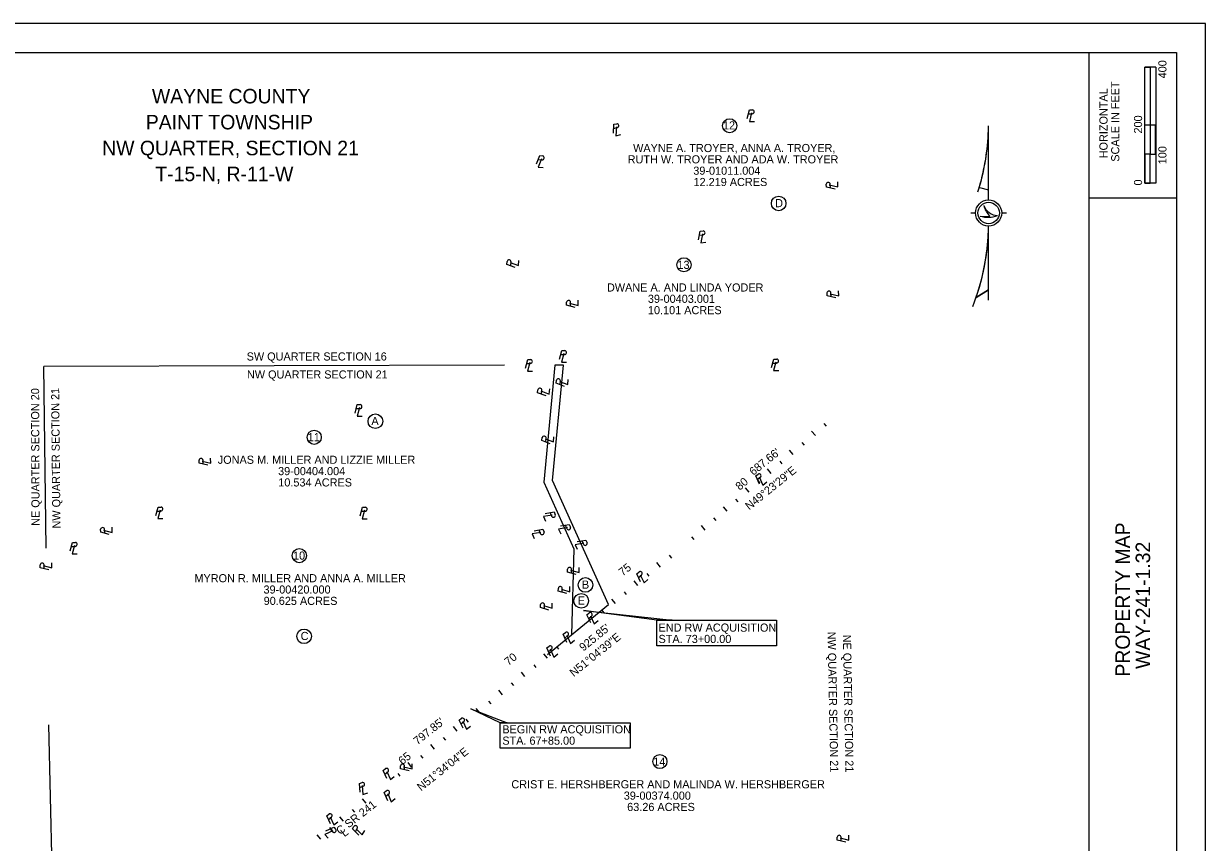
# Model space of a CAD drawing. Extents: x 2180380 to 2187180, y 367894 to 372294.
# Drawn here: x 2183109 to 2187180, y 369473 to 372294 of the extents above; entities that cross this region are included whole.
import ezdxf

# ---------------------------------------------------------------- set-up
doc = ezdxf.new("R2010")
doc.units = 0
for name, color, linetype in [('Default', 7, 'Continuous'), ('DR_X_Elev_Flow', 7, 'Continuous'), ('PM_X_Surveyed_Line', 7, 'Continuous'), ('PV_X_EOP', 7, 'Continuous'), ('PV_X_Shoulder', 7, 'Continuous'), ('RD_X_Cells', 7, 'Continuous'), ('SN_X_Public', 7, 'Continuous'), ('SV_X_Control_Cells_Found', 7, 'Continuous'), ('SV_X_Random_Point', 7, 'Continuous'), ('UT_X_Gas_Cells', 7, 'Continuous'), ('UT_X_Telecom_Cells', 7, 'Continuous'), ('VG_X_Cells', 7, 'Continuous')]:
    doc.layers.add(name, color=color, linetype=linetype)

msp = doc.modelspace()

# ---------------------------------------------------------------- linework, layer by layer
at = {"layer": 'Default'}
for points in [[(2185290.3, 370238.7), (2185038.3, 370271.8), (2185343.4, 370238.7)], [(2185290.3, 370238.7), (2185703, 370238.7), (2185703, 370150.5), (2185290.3, 370150.5)], [(2184750.4, 369884.7), (2184650.2, 369932.6), (2184775, 369884.7)], [(2184750.4, 369884.7), (2185198.3, 369884.7), (2185198.3, 369797.9), (2184750.4, 369797.9)]]:
    msp.add_lwpolyline(points, close=True, dxfattribs=at)
for centre in [(2185541.3, 371942.5), (2185383.9, 371463.3), (2184110.2, 370868.8), (2184059, 370460.9), (2185300.9, 369751.4)]:
    msp.add_circle(centre, 24.3, dxfattribs=at)
at = {"layer": 'DR_X_Elev_Flow'}
for p, q in [((2186971.2, 371744.4), (2186971.2, 372144.4)), ((2187008.7, 372144.4), (2186971.2, 372144.4)), ((2186971.2, 371944.4), (2186971.2, 372144.4)), ((2186971.2, 372144.4), (2186989.9, 372144.4)), ((2186989.9, 372144.4), (2186990, 372144.4)), ((2186990, 372144.4), (2186990, 371944.4)), ((2187008.7, 372144.4), (2187008.7, 371744.4)), ((2186433.3, 371686.8), (2186433.3, 371941.8)), ((2186990, 371944.4), (2186971.2, 371944.4)), ((2187008.5, 371944.4), (2186989.9, 371944.4)), ((2186989.9, 371944.4), (2186989.9, 371844.4)), ((2187008.5, 371844.4), (2187008.5, 371944.4)), ((2186989.9, 371844.4), (2186971.2, 371844.4)), ((2186971.2, 371844.4), (2186971.2, 371744.4)), ((2186989.9, 371844.4), (2187008.5, 371844.4)), ((2186989.9, 371744.4), (2186989.9, 371844.4)), ((2186401.4, 371729.8), (2186433.3, 371721.1)), ((2187008.7, 371744.4), (2186971.2, 371744.4)), ((2186971.2, 371744.4), (2186989.9, 371744.4)), ((2186372.3, 371641.8), (2186388.3, 371641.8)), ((2186478.3, 371641.8), (2186494.3, 371641.8)), ((2186433.3, 371341.8), (2186433.3, 371596.8)), ((2186433.3, 371376.8), (2186390.4, 371351.1))]:
    msp.add_line(p, q, dxfattribs=at)
for points in [[(2186401.2, 371729.9), (2186401.4, 371729.8), (2186433.3, 371721.1), (2186433.3, 371941.8)], [(2186390.4, 371351.1), (2186433.3, 371376.8), (2186433.3, 371596.8)]]:
    msp.add_lwpolyline(points, dxfattribs=at)
for radius in [45, 37]:
    msp.add_circle((2186433.3, 371641.8), radius, dxfattribs=at)
for centre, radius, start, end in [((2185644.8, 371952.9), 788.5, 342.4153, 359.1947), ((2185644.8, 371952.9), 788.5, 343.5754, 359.1947), ((2186464.8, 371684.3), 51, 199.1575, 269.3709), ((2186486.5, 371683.6), 71.7, 192.8556, 227.3141), ((2186431.1, 371717.6), 90.5, 252.4874, 291.486), ((2186422.3, 371744.1), 114.3, 260.7277, 277.8734), ((2185644.8, 371607.9), 788.5, 338.5054, 359.1947), ((2185644.8, 371607.9), 788.5, 340.9936, 359.1947)]:
    msp.add_arc(centre, radius, start, end, dxfattribs=at)
at = {"layer": 'PM_X_Surveyed_Line'}
for p, q in [((2185874.4, 370907.2), (2185866.6, 370916.3)), ((2185836.4, 370874.7), (2185823.4, 370889.9)), ((2185760.5, 370809.6), (2185747.5, 370824.8)), ((2185798.5, 370842.1), (2185790.6, 370851.3)), ((2185722.5, 370777.1), (2185714.7, 370786.2)), ((2185684.6, 370744.5), (2185671.6, 370759.7)), ((2185646.6, 370712), (2185638.8, 370721.1)), ((2185608.7, 370679.4), (2185595.6, 370694.6)), ((2185532.7, 370614.3), (2185519.7, 370629.5)), ((2185570.7, 370646.9), (2185562.9, 370656)), ((2185494.8, 370581.8), (2185487, 370590.9)), ((2185456.8, 370549.2), (2185443.8, 370564.4)), ((2185418.9, 370516.7), (2185411.1, 370525.8))]:
    msp.add_line(p, q, dxfattribs=at)
at = {"layer": 'PV_X_EOP'}
msp.add_lwpolyline([(2184969.3, 371117.5), (2184939.1, 371117.6), (2184901, 370714.4), (2185004.7, 370484.7), (2184997, 370187.9), (2185124.2, 370293), (2184931.6, 370719.6), (2184969.3, 371117.5)], dxfattribs=at)
at = {"layer": 'PV_X_Shoulder'}
for centre in [(2185710.1, 371674.6), (2184321, 370924.1), (2185044.5, 370359.9), (2185030, 370305.2), (2184075.6, 370182.9)]:
    msp.add_circle(centre, 25.2, dxfattribs=at)
at = {"layer": 'RD_X_Cells'}
for p, q in [((2186779.9, 367994.4), (2186779.9, 372194.4)), ((2186779.9, 371694.4), (2187079.9, 371694.4))]:
    msp.add_line(p, q, dxfattribs=at)
msp.add_lwpolyline([(2180679.9, 372194.4), (2187079.9, 372194.4), (2187079.9, 367994.4), (2180679.9, 367994.4)], close=True, dxfattribs=at)
at = {"layer": 'SN_X_Public'}
for p, q in [((2185342, 370452.7), (2185334.5, 370462.1)), ((2185303.1, 370421.3), (2185290.5, 370436.9)), ((2185264.2, 370389.9), (2185256.7, 370399.3)), ((2185186.4, 370327.1), (2185178.9, 370336.4)), ((2185225.3, 370358.5), (2185212.7, 370374.1)), ((2185147.5, 370295.7), (2185134.9, 370311.2)), ((2185108.6, 370264.3), (2185101.1, 370273.6)), ((2184953, 370138.6), (2184945.5, 370147.9)), ((2184914.1, 370107.2), (2184901.6, 370122.8)), ((2184836.3, 370044.4), (2184823.8, 370059.9)), ((2184875.2, 370075.8), (2184867.7, 370085.1)), ((2184797.4, 370013), (2184789.9, 370022.3)), ((2184758.5, 369981.5), (2184746, 369997.1)), ((2184680.7, 369918.7), (2184668.2, 369934.3)), ((2184719.6, 369950.1), (2184712.1, 369959.5)), ((2184641.7, 369887.5), (2184634.2, 369896.9)), ((2184602.5, 369856.4), (2184590.1, 369872.1)), ((2184524.2, 369794.2), (2184511.8, 369809.9)), ((2184563.4, 369825.3), (2184555.9, 369834.7)), ((2184485, 369763.1), (2184477.6, 369772.5)), ((2184445.9, 369732.1), (2184433.4, 369747.7)), ((2184406.7, 369701), (2184399.2, 369710.4)), ((2184289.2, 369607.8), (2184276.8, 369623.4)), ((2184250, 369576.7), (2184242.6, 369586.1)), ((2184171.7, 369514.5), (2184164.2, 369523.9)), ((2184210.8, 369545.6), (2184198.4, 369561.3)), ((2184132.5, 369483.4), (2184120.1, 369499.1))]:
    msp.add_line(p, q, dxfattribs=at)
at = {"layer": 'SV_X_Control_Cells_Found'}
for p, q in [((2184765.3, 371117), (2183179.4, 371113.1)), ((2183187.5, 370486.8), (2183179.4, 371113.1)), ((2183195.4, 369878.1), (2183219.4, 368766.9))]:
    msp.add_line(p, q, dxfattribs=at)
at = {"layer": 'SV_X_Random_Point'}
msp.add_lwpolyline([(2180379.9, 367894.4), (2187179.9, 367894.4), (2187179.9, 372294.4), (2180379.9, 372294.4)], close=True, dxfattribs=at)
at = {"layer": 'UT_X_Telecom_Cells'}
for p, q in [((2185606.3, 371983.8), (2185619.3, 371983.8)), ((2185614.3, 371977.6), (2185614.3, 371977.6)), ((2185141.6, 371933.3), (2185154.3, 371935.9)), ((2185150.7, 371928.8), (2185150.7, 371928.8)), ((2184882.1, 371826.4), (2184894.9, 371824.9)), ((2184889.3, 371819.3), (2184889.3, 371819.3)), ((2185888.2, 371727.7), (2185887.6, 371740.7)), ((2185894.1, 371736), (2185894.1, 371736)), ((2185437.3, 371565.3), (2185450.2, 371566.4)), ((2185445.8, 371559.8), (2185445.8, 371559.8)), ((2184787.1, 371459.8), (2184788.3, 371472.8)), ((2184794, 371467.3), (2184794, 371467.3)), ((2185890.6, 371353), (2185890.3, 371365.9)), ((2185896.7, 371361.1), (2185896.7, 371361.1)), ((2184993.3, 371320.8), (2184993.4, 371333.8)), ((2184999.6, 371328.8), (2184999.6, 371328.8)), ((2184959.3, 371153.7), (2184972.3, 371153.7)), ((2184842.1, 371123.4), (2184855.1, 371123.4)), ((2184850.1, 371117.2), (2184850.1, 371117.2)), ((2184967.3, 371147.5), (2184967.3, 371147.5)), ((2185689.9, 371124.7), (2185702.8, 371124.7)), ((2185697.9, 371118.5), (2185697.9, 371118.5)), ((2184893.3, 371017.6), (2184894.5, 371030.5)), ((2184957.1, 371050.1), (2184958.3, 371063)), ((2184964.1, 371057.5), (2184964.1, 371057.5)), ((2184900.2, 371025), (2184900.2, 371025)), ((2184255, 370967.8), (2184268, 370967.8)), ((2184263, 370961.6), (2184263, 370961.6)), ((2184907.8, 370852.3), (2184909, 370865.2)), ((2184914.7, 370859.7), (2184914.7, 370859.7)), ((2183727.5, 370776.3), (2183727.3, 370789.2)), ((2183733.6, 370784.4), (2183733.6, 370784.4)), ((2185636.9, 370722.8), (2185646.9, 370731)), ((2185647, 370723), (2185647, 370723)), ((2183569.1, 370614.7), (2183582.1, 370614.7)), ((2183577.1, 370608.5), (2183577.1, 370608.5)), ((2184272.9, 370613.9), (2184285.8, 370613.9)), ((2184280.9, 370607.7), (2184280.9, 370607.7)), ((2184920.1, 370599.2), (2184920.1, 370599.2)), ((2184922.5, 370609), (2184927.8, 370597.2)), ((2183388.5, 370537.9), (2183388.3, 370550.8)), ((2183394.6, 370546), (2183394.6, 370546)), ((2184883.6, 370549.4), (2184888.9, 370537.5)), ((2184972.5, 370556), (2184972.5, 370556)), ((2184974.9, 370565.8), (2184980.3, 370554)), ((2184881.2, 370539.5), (2184881.2, 370539.5)), ((2185029.6, 370502.1), (2185029.6, 370502.1)), ((2185032, 370511.9), (2185037.4, 370500.1)), ((2183273.8, 370493), (2183286.7, 370493)), ((2183281.8, 370486.7), (2183281.8, 370486.7)), ((2183180.2, 370415.8), (2183180, 370428.7)), ((2183186.3, 370423.9), (2183186.3, 370423.9)), ((2184996.3, 370400.4), (2184996.6, 370413.4)), ((2185002.7, 370408.3), (2185002.7, 370408.3)), ((2185227.4, 370385.7), (2185237.3, 370394.1)), ((2185237.5, 370386.2), (2185237.5, 370386.2)), ((2184964.6, 370334.6), (2184964.9, 370347.6)), ((2184971, 370342.5), (2184971, 370342.5)), ((2184903.1, 370277.8), (2184903.4, 370290.7)), ((2184909.5, 370285.6), (2184909.5, 370285.6)), ((2185040.9, 370224.1), (2184913.8, 370119)), ((2185055.7, 370244.5), (2185065.7, 370252.8)), ((2185065.9, 370244.8), (2185065.9, 370244.8)), ((2184974, 370176.9), (2184984, 370185.2)), ((2184984.2, 370177.2), (2184984.2, 370177.2)), ((2184917.2, 370129.9), (2184927.2, 370138.2)), ((2184927.4, 370130.3), (2184927.4, 370130.3)), ((2184615.8, 369880.8), (2184625.7, 369889.1)), ((2184625.9, 369881.2), (2184625.9, 369881.2)), ((2184421.6, 369722.9), (2184421.3, 369735.9)), ((2184427.6, 369731.1), (2184427.6, 369731.1)), ((2184353.9, 369707.7), (2184363.9, 369715.8)), ((2184364, 369707.9), (2184364, 369707.9)), ((2184267, 369661.8), (2184279.2, 369666)), ((2184276.6, 369658.5), (2184276.6, 369658.5)), ((2184357.4, 369631.6), (2184367.6, 369639.6)), ((2184367.6, 369631.7), (2184367.6, 369631.7)), ((2184159.5, 369551.3), (2184169.5, 369559.4)), ((2184169.6, 369551.5), (2184169.6, 369551.5)), ((2184165.3, 369519.1), (2184173.6, 369509.1)), ((2184165.6, 369508.9), (2184165.6, 369508.9)), ((2184251.9, 369509), (2184258.4, 369520.2)), ((2184261.3, 369512.8), (2184261.3, 369512.8)), ((2185925.5, 369477.4), (2185925.2, 369490.4)), ((2185931.5, 369485.5), (2185931.5, 369485.5))]:
    msp.add_line(p, q, dxfattribs=at)
for points in [[(2185602.1, 371967.9), (2185609.9, 371997.6), (2185620.3, 371997.6)], [(2185617, 371987.2), (2185609.1, 371957.6), (2185626.6, 371957.6)], [(2185140.7, 371916.8), (2185142.3, 371947.5), (2185152.4, 371949.6)], [(2185151.3, 371938.8), (2185149.6, 371908.2), (2185166.7, 371911.8)], [(2184876.1, 371811.1), (2184887.2, 371839.6), (2184897.5, 371838.4)], [(2184893.1, 371828.5), (2184881.8, 371800.1), (2184899.2, 371798)], [(2185904.3, 371724.2), (2185874.3, 371730.8), (2185873.9, 371741.1)], [(2185884.4, 371738.3), (2185914.2, 371731.6), (2185913.5, 371749.1)], [(2185434.4, 371549.1), (2185439.8, 371579.3), (2185450.1, 371580.1)], [(2185447.7, 371569.6), (2185442.2, 371539.4), (2185459.6, 371540.9)], [(2184784.7, 371470.8), (2184813.5, 371460.3), (2184815, 371477.7)], [(2184802.6, 371454.3), (2184773.8, 371464.7), (2184774.7, 371475)], [(2185906.6, 371349.2), (2185876.8, 371356.2), (2185876.6, 371366.6)], [(2185887, 371363.6), (2185916.8, 371356.4), (2185916.3, 371373.8)], [(2185009.2, 371316.5), (2184979.6, 371324.5), (2184979.7, 371334.8)], [(2184990, 371331.5), (2185019.6, 371323.4), (2185019.7, 371340.9)], [(2184955.1, 371137.8), (2184962.9, 371167.4), (2184973.2, 371167.4)], [(2184970, 371157.1), (2184962.1, 371127.5), (2184979.5, 371127.5)], [(2184837.9, 371107.5), (2184845.7, 371137.2), (2184856, 371137.2)], [(2184852.8, 371126.8), (2184844.9, 371097.2), (2184862.3, 371097.2)], [(2185685.7, 371108.8), (2185693.5, 371138.5), (2185703.8, 371138.4)], [(2185700.5, 371128.1), (2185692.6, 371098.5), (2185710.1, 371098.5)], [(2184908.7, 371011.9), (2184879.9, 371022.5), (2184880.9, 371032.8)], [(2184890.9, 371028.6), (2184919.6, 371017.9), (2184921.3, 371035.3)], [(2184972.5, 371044.4), (2184943.8, 371055), (2184944.8, 371065.3)], [(2184954.7, 371061), (2184983.4, 371050.4), (2184985.1, 371067.8)], [(2184250.8, 370951.9), (2184258.6, 370981.5), (2184269, 370981.5)], [(2184265.7, 370971.2), (2184257.8, 370941.6), (2184275.3, 370941.6)], [(2184923.2, 370846.6), (2184894.5, 370857.2), (2184895.4, 370867.5)], [(2184905.4, 370863.2), (2184934.1, 370852.6), (2184935.8, 370870)], [(2183743.5, 370772.3), (2183713.7, 370779.7), (2183713.6, 370790)], [(2183724, 370786.9), (2183753.7, 370779.4), (2183753.4, 370796.8)], [(2185643.7, 370707.8), (2185630.9, 370735.7), (2185638.9, 370742.2)], [(2185643, 370732.2), (2185655.7, 370704.3), (2185669.2, 370715.4)], [(2183564.9, 370598.8), (2183572.7, 370628.5), (2183583, 370628.5)], [(2184268.7, 370598), (2184276.5, 370627.6), (2184286.8, 370627.6)], [(2183579.8, 370618.1), (2183571.9, 370588.5), (2183589.3, 370588.5)], [(2184283.5, 370617.3), (2184275.6, 370587.7), (2184293.1, 370587.7)], [(2184930, 370600.7), (2184899.7, 370595.7), (2184906.9, 370579.8)], [(2184906.3, 370606.3), (2184936.5, 370611.4), (2184940.7, 370602)], [(2183404.4, 370533.9), (2183374.7, 370541.3), (2183374.6, 370551.6)], [(2183384.9, 370548.5), (2183414.6, 370541), (2183414.4, 370558.5)], [(2184891.1, 370541), (2184860.9, 370536.1), (2184868.1, 370520.1)], [(2184867.4, 370546.6), (2184897.6, 370551.7), (2184901.9, 370542.3)], [(2184982.4, 370557.5), (2184952.2, 370552.5), (2184959.4, 370536.6)], [(2184958.7, 370563.1), (2184988.9, 370568.2), (2184993.2, 370558.8)], [(2183269.6, 370477), (2183277.4, 370506.7), (2183287.7, 370506.7)], [(2185039.5, 370503.6), (2185009.3, 370498.6), (2185016.5, 370482.7)], [(2185015.8, 370509.2), (2185046, 370514.3), (2185050.3, 370504.9)], [(2183284.4, 370496.3), (2183276.5, 370466.8), (2183294, 370466.8)], [(2183196.2, 370411.9), (2183166.4, 370419.1), (2183166.2, 370429.4)], [(2183176.6, 370426.4), (2183206.4, 370419.1), (2183206, 370436.6)], [(2184993.2, 370411.2), (2185022.6, 370402.5), (2185023, 370420)], [(2185012.1, 370395.8), (2184982.7, 370404.4), (2184983, 370414.7)], [(2185234.5, 370370.9), (2185221.2, 370398.6), (2185229.1, 370405.2)], [(2185233.3, 370395.2), (2185246.4, 370367.6), (2185259.7, 370378.9)], [(2184980.4, 370330), (2184951, 370338.6), (2184951.2, 370348.9)], [(2184961.5, 370345.4), (2184990.8, 370336.7), (2184991.3, 370354.2)], [(2184900, 370288.6), (2184929.4, 370279.9), (2184929.8, 370297.3)], [(2184918.9, 370273.2), (2184889.5, 370281.8), (2184889.7, 370292.1)], [(2185062.6, 370229.5), (2185049.8, 370257.4), (2185057.7, 370264)], [(2185061.8, 370253.9), (2185074.6, 370226.1), (2185088, 370237.2)], [(2184980.9, 370162), (2184968, 370189.8), (2184976, 370196.4)], [(2184980.1, 370186.3), (2184992.8, 370158.5), (2185006.3, 370169.6)], [(2184924.1, 370115), (2184911.3, 370142.8), (2184919.2, 370149.4)], [(2184923.3, 370139.4), (2184936, 370111.5), (2184949.5, 370122.7)], [(2184622.8, 369865.9), (2184609.7, 369893.7), (2184617.7, 369900.3)], [(2184621.8, 369890.3), (2184634.8, 369862.5), (2184648.1, 369873.7)], [(2184360.6, 369692.6), (2184348, 369720.6), (2184356.1, 369727.1)], [(2184437.6, 369719.2), (2184407.8, 369726.2), (2184407.5, 369736.5)], [(2184418, 369733.5), (2184447.7, 369726.4), (2184447.3, 369743.9)], [(2184360, 369717), (2184372.5, 369689), (2184386.1, 369700)], [(2184268.2, 369645.4), (2184265.9, 369675.9), (2184275.7, 369679.3)], [(2184276, 369668.4), (2184278.1, 369637.9), (2184294.6, 369643.6)], [(2184364.1, 369616.5), (2184351.7, 369644.6), (2184359.8, 369651)], [(2184363.7, 369640.8), (2184375.9, 369612.8), (2184389.6, 369623.6)], [(2184166.2, 369536.3), (2184153.6, 369564.2), (2184161.7, 369570.7)], [(2184150.4, 369512.1), (2184178.2, 369525.1), (2184184.8, 369517.1)], [(2184165.7, 369560.6), (2184178.1, 369532.7), (2184191.7, 369543.7)], [(2184263.6, 369497.4), (2184241.8, 369519), (2184247, 369528)], [(2184174.7, 369513), (2184146.9, 369500.2), (2184158.1, 369486.8)], [(2184254.4, 369520), (2184276, 369498.3), (2184284.7, 369513.5)], [(2185941.5, 369473.5), (2185911.7, 369480.8), (2185911.5, 369491.1)], [(2185921.9, 369488), (2185951.6, 369480.7), (2185951.3, 369498.2)]]:
    msp.add_lwpolyline(points, dxfattribs=at)
for centre, start, end in [((2185619.2, 371990.7), 270.471, 81.3281), ((2185152.8, 371942.7), 282.2766, 93.1337), ((2184895.7, 371831.8), 263.8916, 74.7487), ((2185880.7, 371740.4), 2.8769, 173.734), ((2185449.6, 371573.3), 275.138, 85.9951), ((2184781.4, 371473.3), 355.3999, 166.2571), ((2185883.4, 371365.7), 1.867, 172.7241), ((2184986.5, 371333.7), 0.1769, 171.034), ((2184972.2, 371160.6), 270.471, 81.3281), ((2184855, 371130.3), 270.471, 81.3281), ((2185702.8, 371131.6), 270.471, 81.3281), ((2184951.4, 371063.6), 355.0649, 165.9221), ((2184887.6, 371031.1), 355.0649, 165.9221), ((2184267.9, 370974.7), 270.471, 81.3281), ((2184902.1, 370865.8), 355.0649, 165.9221), ((2183720.5, 370789.1), 1.2358, 172.0929), ((2185642.5, 370736.3), 309.9088, 120.7659), ((2183582, 370621.6), 270.471, 81.3281), ((2184285.8, 370620.8), 270.471, 81.3281), ((2184934.1, 370600.1), 204.7708, 15.6279), ((2183381.4, 370550.7), 1.2358, 172.0929), ((2184895.2, 370540.4), 204.7708, 15.6279), ((2184986.5, 370556.9), 204.7708, 15.6279), ((2183286.7, 370499.9), 270.471, 81.3281), ((2185043.6, 370503), 204.7708, 15.6279), ((2183173.1, 370428.5), 1.6757, 172.5328), ((2184989.7, 370413.5), 358.9838, 169.8409), ((2185232.7, 370399.4), 310.8028, 121.6599), ((2184958, 370347.7), 358.9838, 169.8409), ((2184896.5, 370290.9), 358.9838, 169.8409), ((2185061.3, 370258), 310.0599, 120.9171), ((2184979.6, 370190.5), 310.0599, 120.9171), ((2184922.8, 370143.5), 310.0599, 120.9171), ((2184621.3, 369894.4), 310.4572, 121.3143), ((2184359.6, 369721.1), 309.5038, 120.3609), ((2184414.4, 369735.7), 1.9741, 172.8312), ((2184276.9, 369672.5), 289.3975, 100.2547), ((2184363.3, 369645), 308.9353, 119.7925), ((2184165.2, 369564.8), 309.5038, 120.3609), ((2184252.4, 369523.6), 330.5024, 141.3595), ((2184178.8, 369513.6), 220.1842, 31.0413), ((2185918.3, 369490.2), 1.603, 172.4601)]:
    msp.add_arc(centre, 6.9, start, end, dxfattribs=at)

# ---------------------------------------------------------------- texts
at = {"layer": 'Default'}
for s, p in [('12', (2185518.3, 371929.7)), ('WAYNE A. TROYER, ANNA A. TROYER, ', (2185208.7, 371851.7)), ('RUTH W. TROYER AND ADA W. TROYER', (2185189.9, 371812.7)), ('39-01011.004', (2185416, 371773.6)), ('12.219 ACRES', (2185416.8, 371734.6)), ('13', (2185361.5, 371449.1)), ('DWANE A. AND LINDA YODER', (2185118.7, 371371.1)), ('39-00403.001', (2185259.6, 371332.1)), ('10.101 ACRES', (2185259.8, 371293)), ('SW QUARTER SECTION 16', (2183877.5, 371133.4)), ('NW QUARTER SECTION 21', (2183878.6, 371071.4)), ('11', (2184088, 370855.4)), ('JONAS M. MILLER AND LIZZIE MILLER', (2183778.1, 370777.4)), ('39-00404.004', (2183985.8, 370738.3)), ('10.534 ACRES', (2183986.5, 370699.3)), ('10', (2184037.3, 370447.2)), ('MYRON R. MILLER AND ANNA A. MILLER', (2183697.7, 370369.2)), ('39-00420.000', (2183935.6, 370330.2)), ('90.625 ACRES', (2183936.2, 370291.1)), ('END RW ACQUISITION', (2185296.2, 370198.9)), ('STA. 73+00.00', (2185296.2, 370159.9)), ('BEGIN RW ACQUISITION', (2184758.2, 369848.4)), ('STA. 67+85.00', (2184758.2, 369809.4)), ('14', (2185278.1, 369737)), ('CRIST E. HERSHBERGER AND MALINDA W. HERSHBERGER', (2184789.4, 369659)), ('39-00374.000', (2185176.5, 369619.9)), ('63.26 ACRES', (2185188.3, 369580.9))]:
    msp.add_text(s, height=28, dxfattribs=at).set_placement(p)
for s, rotation, p in [('NE QUARTER SECTION 20', 90.1877, (2183164.3, 370563.6)), ('NW QUARTER SECTION 21', 90.5777, (2183236.5, 370554.6)), ('NW QUARTER SECTION 21', 271.0986, (2185878.5, 370198.6)), ('NE QUARTER SECTION 21', 271.0986, (2185931.2, 370188.2)), ('C SR 241', 38.3277, (2184199.6, 369497.3)), ('L', 37.5862, (2184214.3, 369490.2))]:
    msp.add_text(s, height=28, rotation=rotation, dxfattribs=at).set_placement(p)
at = {"layer": 'DR_X_Elev_Flow'}
for s, height, p in [('400', 28, (2187045.9, 372105.7)), ('SCALE IN FEET', 28, (2186883.4, 371818.5)), ('HORIZONTAL', 28, (2186842.9, 371830.2)), ('200', 28, (2186962, 371915.7)), ('100', 28, (2187045.9, 371809.7)), ('0', 28, (2186962, 371736.6)), ('PROPERTY MAP', 50, (2186920, 370044)), ('WAY-241-1.32', 50, (2186989.7, 370070.4))]:
    msp.add_text(s, height=height, rotation=90, dxfattribs=at).set_placement(p)
for s, p in [('               WAYNE COUNTY               ', (2183272.5, 372019.4)), ('              PAINT TOWNSHIP              ', (2183270.1, 371930)), ('          NW QUARTER, SECTION 21          ', (2183194, 371840.7)), ('              T-15-N, R-11-W              ', (2183303, 371751.4))]:
    msp.add_text(s, height=50, dxfattribs=at).set_placement(p)
at = {"layer": 'PM_X_Surveyed_Line'}
msp.add_text('80', height=28, rotation=40.6088, dxfattribs=at).set_placement((2185576.1, 370684.4))
at = {"layer": 'PV_X_Shoulder'}
for s, p in [('D', (2185698, 371661.8)), ('A', (2184307.2, 370911)), ('B', (2185032.4, 370347.1)), ('E', (2185017.9, 370292.4)), ('C', (2184063.5, 370170.1))]:
    msp.add_text(s, height=28, dxfattribs=at).set_placement(p)
at = {"layer": 'SN_X_Public'}
for s, rotation, p in [('75', 38.9226, (2185172.8, 370389)), ('70', 38.9226, (2184779.3, 370080.4)), ('65', 38.4323, (2184413.9, 369738.7))]:
    msp.add_text(s, height=28, rotation=rotation, dxfattribs=at).set_placement(p)
at = {"layer": 'UT_X_Gas_Cells'}
for s, rotation, p in [("687.66'", 38.9226, (2185623, 370735.4)), ("925.85'", 38.9226, (2185037.1, 370130)), ("797.85'", 38.4323, (2184465.9, 369807.2))]:
    msp.add_text(s, height=28, rotation=rotation, dxfattribs=at).set_placement(p)
at = {"layer": 'VG_X_Cells'}
for s, rotation, p in [('N49°23\'29"E', 38.9226, (2185608.8, 370616.4)), ('N51°04\'39"E', 38.9226, (2185004, 370042)), ('N51°34\'04"E', 38.4323, (2184478.2, 369648.3))]:
    msp.add_text(s, height=28, rotation=rotation, dxfattribs=at).set_placement(p)

doc.saveas('drawing.dxf')
